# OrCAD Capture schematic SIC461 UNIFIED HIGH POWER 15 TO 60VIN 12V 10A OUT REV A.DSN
size B; title: SIC461 Demo High Power Unified Board 15 to 60Vin 12Vout 10A 300kHz; rev: A
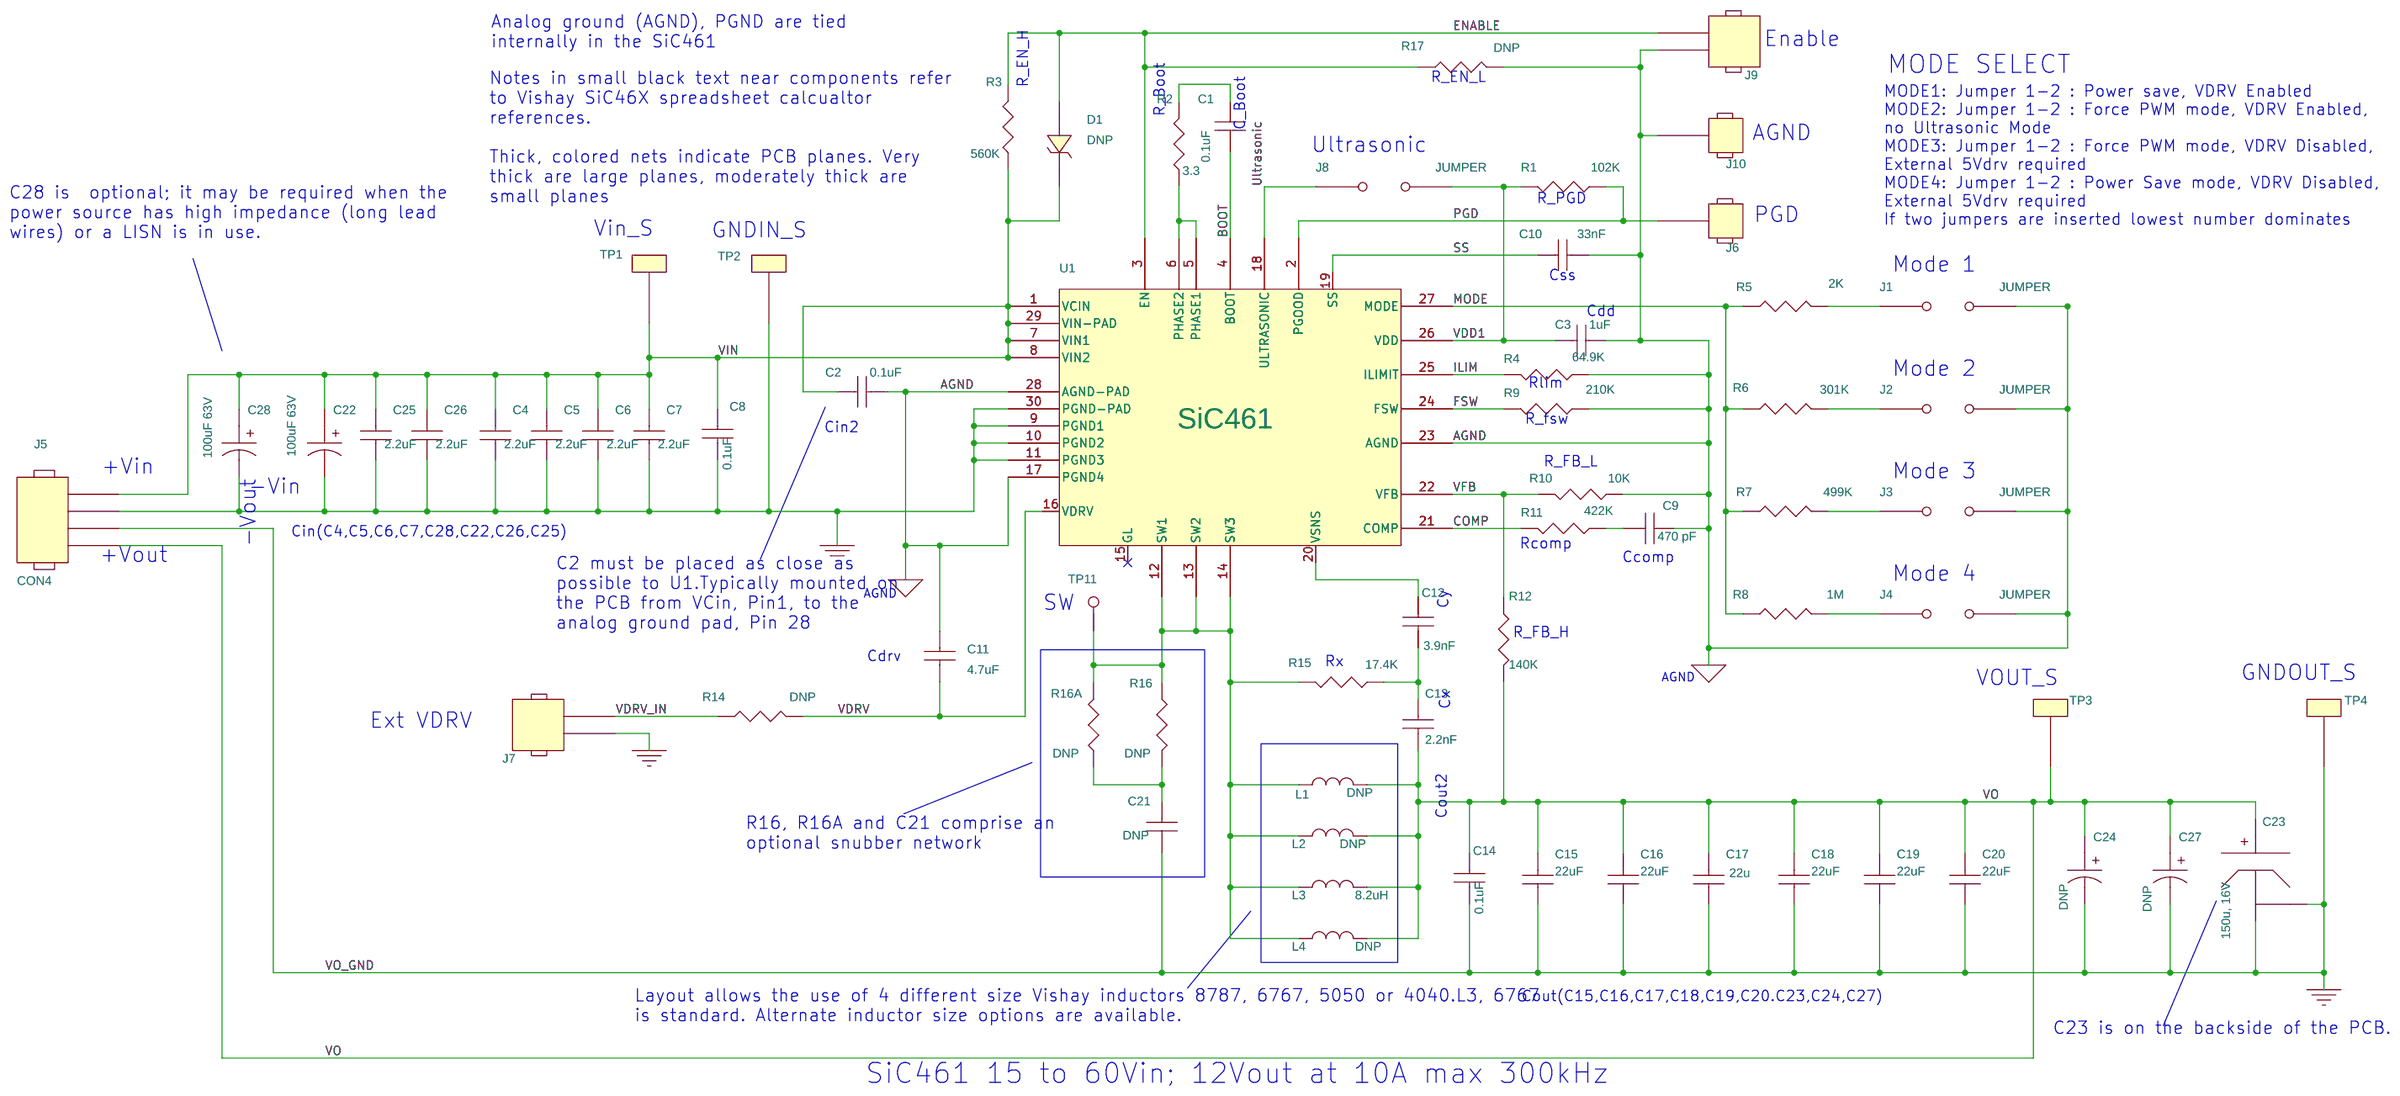
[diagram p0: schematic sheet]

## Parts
C1  0.1uF  [C0603]
C2  0.1uF  [C0603]
C3  1uF  [C0603]
C4  2.2uF  [C1210]
C5  2.2uF  [C1210]
C6  2.2uF  [C1210]
C7  2.2uF  [C1210]
C8  0.1uF  [C0603]
C9  470 pF  [C0603]
C10  33nF  [C0603]
C11  4.7uF  [C0603]
C12  3.9nF  [C0603]
C13  2.2nF  [C0805]
C14  0.1uF  [C0603]
C15  22uF  [C1206]
C16  22uF  [C1206]
C17  22u  [C1206]
C18  22uF  [C1206]
C19  22uF  [C1206]
C20  22uF  [C1206]
C21  DNP  [C0603]
C22  100uF 63V
C23  150u, 16V  [T_D27_7343]
C24  DNP
C25  2.2uF  [C1210]
C26  2.2uF  [C1210]
C27  DNP
C28  100uF 63V
D1  DNP
J1  JUMPER
J2  JUMPER
J3  JUMPER
J4  JUMPER
J5  CON4
J6  PGD  [5002]
J7  EN
J8  JUMPER
J9  EN
J10  GND  [5002]
L1  DNP  [IHLP-4040]
L2  DNP  [IHLP-5050]
L3  8.2uH  [IHLP-6767]
L4  DNP  [IHLP-5050]
R1  102K  [R0603]
R2  3.3  [R0603]
R3  560K  [R0603]
R4  64.9K  [R0603]
R5  2K  [R0603]
R6  301K  [R0603]
R7  499K  [R0603]
R8  1M  [R0603]
R9  210K  [R0603]
R10  10K  [R0603]
R11  422K  [R0603]
R12  140K  [R0603]
R14  DNP  [R0603]
R15  17.4K  [R0805]
R16  DNP  [R0603]
R16A  DNP  [R1210]
R17  DNP  [R0603]
TP1  test point  [5002]
TP2  test point  [5002]
TP3  test point  [5002]
TP4  test point  [5002]
TP11  5002  [PAD040_060_SQ]
U1  SiC461  [5mmx5mm]

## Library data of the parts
C1 C2 C8 C14 = CAP_NP: Ceramic Cap, 0.1uF,100volts, X7S, 10%, 0603; DIGI-KEY: 810-C1608X7S2A104K; Data sheet\: http://www.mouser.com/ds/2/400/lcc_commercial_general_en-837201.pdf; Description1: Ceramic Cap, 0.1uF,100volts, X7S, 10%, 0603; Description2: Ceramic Cap, 0.1uF,100volts, X7S, 10%, 0603; DigikeyMouser: 810-C1608X7S2A104K; Mfr: Murata Electronics; Mfr Part Number: C1608X7S2A104K080AB; PCB Footprint1: 0603; PCB Footprint2: 0603; Package: 0603; Package1: 0603; Package2: 0603; Tolerance: 10%
C3 = CAP_NP: Ceramic Cap, 1uF,50V, X7R,0603,10%; Comment: X7R; DIGI-KEY: 963-UMK107AB7105KA-T; Data sheet\: http://www.mouser.com/ds/2/396/mlcc11_hq_e-541564.pdf; Description1: Ceramic Cap, 1uF,50V, X7R,0603,10%; Description2: Ceramic Cap, 1uF,50V, X7R,0603,10%; DigikeyMouser: 963-UMK107AB7105KA-T; Manufacturer: Taiyo Yuden; Manufacturer Part: UMK107AB7105KA-T; Manufacturer Part1: UMK107AB7105KA-T; Manufacturer Part2: UMK107AB7105KA-T; Manufacturer1: Taiyo Yuden; Manufacturer2: Taiyo Yuden; Mfr: Taiyo Yuden; Mfr Part Number: UMK107AB7105KA-T; Package: 0603; Package1: 0603; Package2: 0603; Tolerance: 10%; Voltage: 50V
C4-C7 C25 C26 = CAP_NP: Ceramic Cap, 2.2uF,100volts, X7R, 10%, 1210; DIGI-KEY: 81-GRM32ER72A225KA5K; Data sheet\: http://www.mouser.com/ds/2/281/c02e-2905.pdf; Description1: Ceramic Cap, 2.2uF,100volts, X7R, 10%, 1210; Description2: Ceramic Cap, 2.2uF,100volts, X7R, 10%, 1210; DigikeyMouser: 81-GRM32ER72A225KA5K; Mfr: Murata Electronics; Mfr Part Number: GRM32ER72A225KA35K
C9 = CAP_NP: Ceramic Cap, 470 pF,50V,C0G,0603,5%; Comment: C0G; DIGI-KEY: 77-VJ0603A471JXAAC; Data sheet\: http://www.mouser.com/ds/2/427/vjcommercialseries-222796.pdf; Description1: Ceramic Cap, 1000pF,50V,C0G,0603,5%; Description2: Ceramic Cap, 1000pF,50V,C0G,0603,5%; DigikeyMouser: 77-VJ0603A471JXAAC; Manufacturer: Vishay; Manufacturer Part: VJ0603A471JXAAC; Manufacturer Part1: VJ0603A471JXAAC; Manufacturer Part2: VJ0603A471JXAAC; Manufacturer1: Vishay; Manufacturer2: Vishay; Mfr: Vishay; Mfr Part Number: VJ0603A471JXAAC; Package: 0603; Package1: 0603; Package2: 0603; Tolerance: 10%; Voltage: 50V
C10 = CAP_NP: Ceramic Cap, 0.033uF,50V,X7R,0603,10%; Comment: X7R; DIGI-KEY: 77-VJ0603Y333KXACBC; Data sheet\: http://www.mouser.com/ds/2/427/vjw1bcbascomseries-223529.pdf; Description1: Ceramic Cap, 0.033uF,50V,X7R,0603,10%; Description2: Ceramic Cap, 0.033uF,50V,X7R,0603,10%; DigikeyMouser: 77-VJ0603Y333KXACBC; Manufacturer: Vishay; Manufacturer Part: VJ0603Y333KXACW1BC; Manufacturer Part1: VJ0603Y333KXACW1BC; Manufacturer Part2: VJ0603Y333KXACW1BC; Manufacturer1: Vishay; Manufacturer2: Vishay; Mfr: Vishay / Vitramon; Mfr Part Number: VJ0603Y333KXACW1BC; Package: 0603; Package1: 0603; Package2: 0603; Tolerance: 10%; Voltage: 50V
C11 = CAP_NP: Ceramic Cap, 4.7uF,25V,X6S,10%,0603; Comment: X6S; DIGI-KEY: 81-GRM188C81E475KE1D; Data sheet\: http://www.mouser.com/ds/2/281/c02e-2905.pdf; Description1: Ceramic Cap, 4.7uF,25V,X6S,10%,0603; Description2: Ceramic Cap, 4.7uF,25V,X6S,10%,0603; DigikeyMouser: 81-GRM188C81E475KE1D; Mfr: Murata; Mfr Part Number: GRM188C81E475KE11D; Tolerance: 10%; Voltage: 25V
C12 = CAP_NP: Ceramic Cap, 3900pF,100V,X7R,0603, 5%; Comment: X7R; DIGI-KEY: 77-VJ0603Y392JXBCBC; Data sheet\: http://www.mouser.com/ds/2/427/vjw1bcbascomseries-223529.pdf; Description1: Ceramic Cap, 3900pF,100V,X7R,0603, 5%; Description2: Ceramic Cap, 3900pF,100V,X7R,0603, 5%; DigikeyMouser: 77-VJ0603Y392JXBCBC; Manufacturer: Vishay; Manufacturer Part: VJ0603Y392JXBCW1BC; Manufacturer Part1: VJ0603Y392JXBCW1BC; Manufacturer Part2: VJ0603Y392JXBCW1BC; Manufacturer1: Vishay; Manufacturer2: Vishay; Mfr: Vishay; Mfr Part Number: VJ0603Y392JXBCW1BC; Package: 0603; Package1: 0603; Package2: 0603; Tolerance: 5%; Voltage: 100V
C13 = CAP_NP: Ceramic Cap, 2200pF,100V,X7R,0805, 10%; Comment: X7R; DIGI-KEY: 77-VJ0805Y222KXBPBC; Data sheet\: http://www.mouser.com/ds/2/427/vjw1bcbascomseries-223529.pdf; Description1: Ceramic Cap, 2200pF,100V,X7R,0805, 10%; Description2: Ceramic Cap, 2200pF,100V,X7R,0805, 10%; DigikeyMouser: 77-VJ0805Y222KXBPBC; Manufacturer: Vishay; Manufacturer Part: VJ0805Y222KXBPW1BC; Manufacturer Part1: VJ0805Y222KXBPW1BC; Manufacturer Part2: VJ0805Y222KXBPW1BC; Manufacturer1: Vishay; Manufacturer2: Vishay; Mfr: Vishay / Vitramon; Mfr Part Number: VJ0805Y222KXBPW1BC; Package: 0805; Package1: 0805; Package2: 0805; Tolerance: 10%; Voltage: 100V
C15 C16 C18-C20 = CAP_NP: Ceramic Cap, 22uF,25volts,X7R,10%,1206; Comment: X7R; DIGI-KEY: 581-12061C225KAT2A; Data sheet\: http://www.mouser.com/ds/2/40/X7RDielectric-777024.pdf; Description1: Ceramic Cap, 22uF,25volts,X7R,10%,1206; Description2: Ceramic Cap, 22uF,25volts,X7R,10%,1206; DigikeyMouser: 581-12061C225KAT2A; Mfr: AVX Corporation; Mfr Part Number: 12061C225KAT2A; Tolerance: 10%; Voltage: 100V
C17 = CAP_NP: Ceramic Cap, 22uF,25volts,X7R,10%,1206; Comment: X7R; DIGI-KEY: 581-12061C225KAT2A; Data sheet\: http://www.mouser.com/ds/2/40/X7RDielectric-777024.pdf; Description1: Ceramic Cap, 22uF,25volts,X7R,10%,1206; Description2: Ceramic Cap, 22uF,25volts,X7R,10%,1206; DigikeyMouser: 581-12061C225KAT2A; Mfr: AVX Corporation; Mfr Part Number: 12061C225KAT2A; Tolerance: 10%; Value1: 22uF; Value2: 22uF; Voltage: 100V
C21 = CAP_NP: Comment: X7S; Data sheet\: http://www.digikey.com/product-detail/en/C1608X7S2A104K080AB/445-5201-2-ND/2116317; DigikeyMouser: 445-5201-2-ND; Mfr: TDK Corporation; Mfr Part Number: C1608X7S2A104K080AB; Package: 0603; Package1: 0603; Package2: 0603; Tolerance: 10%; Voltage: 100V
C22 C24 C27 C28 = CAP_POL: CAP, alum, 100uF, 63volt, 105C, 10x12, 4khr; DIGI-KEY: 594-2222-150-58101; Data sheet\: http://www.mouser.com/ds/2/427/150rmi-222630.pdf; DigikeyMouser: 594-2222-150-58101; Manufacturer: Vishay; Mfr: Vishay; Mfr Part Number: MAL215058101E3; Part Type: CAP POL; Rating: 63V; Tolerance: 20%
C23 = CAP,_TA-P,V,470u,_2V_0: Polymer SMD 16volts 150uF ESR 50mohm 7343; DIGI-KEY: 667-16TQC150MYF; Data sheet\: http://www.mouser.com/ds/2/315/AAA8000C54-931458.pdf; DigikeyMouser: 667-16TQC150MYF; Mfr: Panasonic; Mfr Part Number: 16TQC150MYF
D1 = DIODE_ZENER: DIGI-KEY: 78-BZX384C3V3-E3-08; Data sheet\: http://www.mouser.com/ds/2/427/bzx384-58924.pdf; DigikeyMouser: 78-BZX384C3V3-E3-08; Mfr: Vishay; Mfr Part Number: BZX384C3V3-E3-08
J1-J4 J8 = JUMPER: BREAKAWAY HDR VERT 2 pitch 100mils; DIGI-KEY: 538-22-28-4023; Data sheet\: http://www.mouser.com/ds/2/276/0022284023_PCB_HEADERS-228360.pdf; Description1: BREAKAWAY HDR VERT 2 pitch 100mils; Description2: BREAKAWAY HDR VERT 2pitch 100mils; DigikeyMouser: 538-22-28-4023; Manufacturer: Molex; Manufacturer Part: 22-28-4023; Manufacturer Part1: 22-28-4023; Manufacturer Part2: 22-28-4023; Manufacturer1: Molex; Manufacturer2: Molex; Mfr: Molex; Mfr Part Number: 22-28-4023
J5 = HEADER_4: TERMINAL BLOCK 3.81MM Horz 4POS; DIGI-KEY: 649-220327-D041B01LF; Data sheet\: http://www.mouser.com/ds/2/18/20020327-941783.pdf; Description1: T; DigikeyMouser: 649-220327-D041B01LF; Man: Amphenol Anytek; Mfr: Amphenol Anytek; Mfr Part Number: 20020327-D041B01LF; Rating: 10A
J6 J10 = HEADER_1: Circuit Board Hardware-PCB TEST POINT WHITE; Description1: Circuit Board Hardware-PCB TEST POINT WHITE; Description2: Circuit Board Hardware-PCB TEST POINT WHITE; Man1: Keystone Electronics; Man2: Keystone Electronics; Manufacturer: Keystone Electronics; Manufacturer1: Keystone Electronics; Manufacturer2: Keystone Electronics
J7 J9 = HEADER_2: BREAKAWAY HDR VERT 2 pitch 100mils; DIGI-KEY: 538-22-28-4023; Data sheet\: http://www.mouser.com/ds/2/276/0022284023_PCB_HEADERS-228360.pdf; Description1: BREAKAWAY HDR VERT 2 pitch 100mils; Description2: BREAKAWAY HDR VERT 2 pitch 100mils; DigikeyMouser: 538-22-28-4023; Manufacturer: Molex; Manufacturer Part: 22-28-4023; Manufacturer Part1: 22-28-4023; Manufacturer Part2: 22-28-4023; Manufacturer1: Molex; Manufacturer2: Molex; Mfr: Molex; Mfr Part Number: 22-28-4023
L1 = IND: INDUCTOR, 3.3uH,20%,14m DCR,18.6A Saturation; Current: 8A; Data sheet\: http://www.vishay.com/docs/34193/lp40dz01.pdf; Description1: INDUCTOR, 5.6uH,20%,19m DCR,16A Saturation; Description2: INDUCTOR, 10uH,20%,17.2m DCR,15.5A Saturation; DigikeyMouser: 541-1295-1-ND; Manufacturer: Vishay; Manufacturer Part: IHLP4040DZER3R3M11; Manufacturer Part1: IHLP4040DZER5R6M01; Manufacturer Part2: IHLP5050FDER100M01; Manufacturer1: Vishay; Manufacturer2: Vishay; Mfr: Vishay Dale; Mfr Part Number: IHLP4040DZER100M01; Package1: 4040; Package2: 5050; Value1: 5.6uH; Value2: 10uH
L2 = IND: INDUCTOR, 10uH,20%,4m DCR,28A Saturation; Current: 28A; DIGI-KEY: 70-IHLP8787MZER100M5A; Data sheet\: http://www.mouser.com/ds/2/427/ihlp8787mz5a-211370.pdf; Description1: INDUCTOR, 10uH,20%,4m DCR,28A Saturation; Description2: INDUCTOR, 10uH,20%,4m DCR,28A Saturation; DigikeyMouser: 70-IHLP8787MZER100M5A; Manufacturer: Vishay; Manufacturer Part: IHLP8787MZER100M5A; Manufacturer Part1: IHLP8787MZER100M5A; Manufacturer Part2: IHLP8787MZER100M5A; Manufacturer1: Vishay; Manufacturer2: Vishay; Mfr: Vishay Dale; Mfr Part Number: IHLP8787MZER100M5A; Package1: 8787; Package2: 8787; Value1: 10uH; Value2: 10uH
L3 = IND: INDUCTOR, 8.2uH,20%,8.1m DCR,18.0A Saturation; Current: 18A; DIGI-KEY: 70-IHLP6767GZER8R2M1; Data sheet\: http://www.mouser.com/ds/2/427/lp67gz11-270733.pdf; Description1: INDUCTOR, 8.2uH,20%,8.1m DCR,18.0A Saturation; Description2: INDUCTOR, 8.2uH,20%,8.1m DCR,18.0A Saturation; DigikeyMouser: 70-IHLP6767GZER8R2M1; Manufacturer: Vishay; Manufacturer Part: VJ0603Y122JXBCW1BC; Manufacturer Part1: VJ0603Y122JXBCW1BC; Manufacturer Part2: VJ0603Y122JXBCW1BC; Manufacturer1: Vishay; Manufacturer2: Vishay; Mfr: Vishay Dale; Mfr Part Number: IHLP6767GZER8R2M11; Package1: 6767; Package2: 8787; Value2: 10uH
L4 = IND: INDUCTOR, 3.3uH,20%,14m DCR,18.6A Saturation; Current: 8A; Data sheet\: http://www.vishay.com/docs/34193/lp40dz01.pdf; Description1: INDUCTOR, 5.6uH,20%,19m DCR,16A Saturation; Description2: INDUCTOR, 10uH,20%,17.2m DCR,15.5A Saturation; DigikeyMouser: 541-1295-1-ND; Manufacturer: Vishay; Manufacturer Part: IHLP4040DZER3R3M11; Manufacturer Part1: IHLP6767GZER150M5A; Manufacturer Part2: IHLP5050FDER100M01; Manufacturer1: Vishay; Manufacturer2: Vishay; Mfr: Vishay Dale; Mfr Part Number: IHLP4040DZER100M01; Package1: 4040; Package2: 5050; Value1: 5.6uH; Value2: 10uH
R1 = RESISTOR: SMD,102K,1%,0603; DIGI-KEY: 71-CRCW0603-102K-E3; Data sheet\: http://www.mouser.com/ds/2/427/dcrcwe3-109170.pdf; Description1: SMD,102K,1%,0603; Description2: SMD,102K,1%,0603; DigikeyMouser: 71-CRCW0603-102K-E3; Man: Vishay; Man Part Number: CRCW0603102KFKEA; Man Part Number1: CRCW0603102KFKEA; Man Part Number2: CRCW0603102KFKEA; Man1: Vishay; Man2: Vishay; Manufacturer: Vishay; Manufacturer Part: CRCW0603102KFKEA; Manufacturer Part1: CRCW0603102KFKEA; Manufacturer Part2: CRCW0603102KFKEA; Manufacturer1: Vishay; Manufacturer2: Vishay; Mfr: Vishay; Mfr Part Number: CRCW0603102KFKEA; PCB Footprint1: 0603; PCB Footprint2: 0603; Package: 0603; Package1: 0603; Package2: 0603
R2 = RESISTOR: SMD,3.3Ohm, 1% 0603; DIGI-KEY: 71-CRCW06033R30FKEA; Data sheet\: http://www.mouser.com/ds/2/427/dcrcwe3-109170.pdf; Description1: SMD,3.3Ohm, 1% 0603; Description2: SMD,3.3Ohm, 1% 0603; DigikeyMouser: 71-CRCW06033R30FKEA; Man: Vishay; Man Part Number: CRCW06033R30FKEA; Man Part Number1: CRCW06033R30FKEA; Man Part Number2: CRCW06033R30FKEA; Man1: Vishay; Man2: Vishay; Manufacturer: Vishay; Manufacturer Part: CRCW06030000ZSTA; Manufacturer Part1: CRCW06030000ZSTA; Manufacturer Part2: CRCW06030000ZSTA; Manufacturer1: Vishay; Manufacturer2: Vishay; Mfr: Vishay; Mfr Part Number: CRCW06033R30FKEA; PCB Footprint1: 0603; PCB Footprint2: 0603; Package: 0603; Package1: 0603; Package2: 0603
R3 = RESISTOR: SMD,560K,1%,0603; DIGI-KEY: 71-CRCW0603-560K-E3; Data sheet\: http://www.mouser.com/ds/2/427/dcrcwe3-109170.pdf; Description1: SMD,560K,1%,0603; Description2: SMD,560K,1%,0603; DigikeyMouser: 71-CRCW0603-560K-E3; Man: Vishay; Man Part Number: CRCW0603560KFKEA; Man Part Number1: CRCW0603560KFKEA; Man Part Number2: CRCW0603560KFKEA; Man1: Vishay; Man2: Vishay; Manufacturer: Vishay; Manufacturer Part: CRCW0603560KFKTA; Manufacturer Part1: CRCW0603560KFKTA; Manufacturer Part2: CRCW0603560KFKTA; Manufacturer1: Vishay; Manufacturer2: Vishay; Mfr: Vishay; Mfr Part Number: CRCW0603560KFKEA; PCB Footprint1: 0603; PCB Footprint2: 0603; Package: 0603; Package1: 0603; Package2: 0603
R4 = RESISTOR: SMD,64.9k,1%,0603; DIGI-KEY: 71-CRCW0603-64.9K; Data sheet\: http://www.digikey.com/product-detail/en/vishay-dale/CRCW04024K64FKED/541-4.64KLCT-ND/1183198; Description1: SMD,64.9K,1%,0603; Description2: SMD,64.9K,1%,0603; DigikeyMouser: 71-CRCW0603-64.9K; Manufacturer: Vishay; Manufacturer Part: CRCW060364K9FKTA; Manufacturer Part1: CRCW060364K9FKTA; Manufacturer Part2: CRCW060364K9FKTA; Manufacturer1: Vishay; Manufacturer2: Vishay; Mfr: Vishay Dale; Mfr Part Number: CRCW060364K9FKTA; Package: 0603; Package1: 0603; Package2: 0603; Tolerance: 1%
R5 = RESISTOR: SMD,2K,1%,0603; DIGI-KEY: 71-CRCW06032K00FKEB; Data sheet\: http://www.mouser.com/ds/2/427/dcrcwe3-109170.pdf; Description1: SMD,2K,1%,0603; Description2: SMD,2K,1%,0603; DigikeyMouser: 71-CRCW06032K00FKEB; Manufacturer: Vishay; Manufacturer Part: CRCW06032K00FKEB; Manufacturer Part1: CRCW06032K00FKEB; Manufacturer Part2: CRCW06032K00FKEB; Manufacturer1: Vishay; Manufacturer2: Vishay; Mfr: Vishay Dale; Mfr Part Number: CRCW06032K00FKEB; Package: 0603; Package1: 0603; Package2: 0603; Tolerance: 1%
R6 = RESISTOR: SMD,301K,1%,0603; DIGI-KEY: 71-CRCW0603-301K-E3; Data sheet\: http://www.mouser.com/ds/2/427/dcrcwe3-109170.pdf; Description1: SMD,301K,1%,0603; Description2: SMD,301K,1%,0603; DigikeyMouser: 71-CRCW0603-301K-E3; Manufacturer: Vishay; Manufacturer Part: CRCW0603301KFKEA; Manufacturer Part1: CRCW0603301KFKEA; Manufacturer Part2: CRCW0603301KFKEA; Manufacturer1: Vishay; Manufacturer2: Vishay; Mfr: Vishay Dale; Mfr Part Number: CRCW0603301KFKEA; Package: 0603; Package1: 0603; Package2: 0603; Tolerance: 1%
R7 = RESISTOR: SMD,499K,1%,0603; DIGI-KEY: 71-CRCW0603-499K-E3; Data sheet\: http://www.mouser.com/ds/2/427/dcrcwe3-109170.pdf; Description1: SMD,499K,1%,0603; Description2: SMD,499K,1%,0603; DigikeyMouser: 71-CRCW0603-499K-E3; Manufacturer: Vishay; Manufacturer Part: CRCW0603499KFKEA; Manufacturer Part1: CRCW0603499KFKEA; Manufacturer Part2: CRCW0603499KFKEA; Manufacturer1: Vishay; Manufacturer2: Vishay; Mfr: Vishay Dale; Mfr Part Number: CRCW0603499KFKEA; Package: 0603; Package1: 0603; Package2: 0603; Tolerance: 1%
R8 = RESISTOR: SMD,1000K,1%,0603; DIGI-KEY: 71-RCG06031M00FKEA; Data sheet\: http://www.mouser.com/ds/2/427/rcge3-254226.pdf; Description1: SMD,1000K,1%,0603; Description2: SMD,1000K,1%,0603; DigikeyMouser: 71-RCG06031M00FKEA; Manufacturer: Vishay; Manufacturer Part: RCG06031M00FKEA; Manufacturer Part1: RCG06031M00FKEA; Manufacturer Part2: RCG06031M00FKEA; Manufacturer1: Vishay; Manufacturer2: Vishay; Mfr: Vishay Dale; Mfr Part Number: RCG06031M00FKEA; Package: 0603; Package1: 0603; Package2: 0603; Tolerance: 1%
R9 = RESISTOR: SMD,210K,1%,0603 100PPM; DIGI-KEY: 71-CRCW0603-210K-E3; Data sheet\: http://www.mouser.com/ds/2/427/dcrcwe3-109170.pdf; Description1: SMD,210K,1%,0603 100PPM; Description2: SMD,210K,1%,0603 100PPM; DigikeyMouser: 71-CRCW0603-210K-E3; Manufacturer: Vishay; Manufacturer Part: CRCW0603210KFKEA; Manufacturer Part1: CRCW0603210KFKEA; Manufacturer Part2: CRCW0603210KFKEA; Manufacturer1: Vishay; Manufacturer2: Vishay; Mfr: Vishay Dale; Mfr Part Number: CRCW0603210KFKEA; Package: 0603; Package1: 0603; Package2: 0603; Tolerance: 1%
R10 = RESISTOR: SMD,10K,1%,0603; DIGI-KEY: 71-CRCW0603-10K; Data sheet\: http://www.mouser.com/ds/2/427/dcrcwe3-109170.pdf; Description1: SMD,10K,1%,0603; Description2: SMD,10K,1%,0603; DigikeyMouser: 71-CRCW0603-10K; Manufacturer: Vishay; Manufacturer Part: CRCW060310K0FKTA; Manufacturer Part1: CRCW060310K0FKTA; Manufacturer Part2: CRCW060310K0FKTA; Manufacturer1: Vishay; Manufacturer2: Vishay; Mfr: Vishay Dale; Mfr Part Number: CRCW060310K0FKTA; Package: 0603; Package1: 0603; Package2: 0603; Tolerance: 1%
R11 = RESISTOR: SMD 1/10watt 422Kohms 1%,0603; DIGI-KEY: 71-CRCW0603-422K-E3; Data sheet\: http://www.mouser.com/ds/2/427/dcrcwe3-109170.pdf; Description1: SMD 1/10watt 422Kohms 1%,0603; Description2: SMD 1/10watt 422Kohms 1%,0603; DigikeyMouser: 71-CRCW0603-422K-E3; Manufacturer: Vishay; Manufacturer Part: CRCW0603422KFKEA; Manufacturer Part1: CRCW0603422KFKEA; Manufacturer Part2: CRCW0603422KFKEA; Manufacturer1: Vishay; Manufacturer2: Vishay; Mfr: Vishay Dale; Mfr Part Number: CRCW0603422KFKEA; Package: 0603; Package1: 0603; Package2: 0603; Tolerance: 1%
R12 = RESISTOR: SMD 1,10W 140K Ohms 1% 0603; DIGI-KEY: 71-CRCW0603-140K-E3; Data sheet\: http://www.mouser.com/ds/2/427/dcrcwe3-109170.pdf; Description1: SMD 1,10W 140K Ohms 1% 0603; Description2: SMD 1,10W 140K Ohms 1% 0603; DigikeyMouser: 71-CRCW0603-140K-E3; Manufacturer: Vishay; Manufacturer Part: CRCW0603140KFKEA; Manufacturer Part1: CRCW0603140KFKEA; Manufacturer Part2: CRCW0603140KFKEA; Manufacturer1: Vishay; Manufacturer2: Vishay; Mfr: Vishay Dale; Mfr Part Number: CRCW0603140KFKEA; Package: 0603; Package1: 0603; Package2: 0603; Tolerance: 1%
R14 R16 = RESISTOR: Data sheet\: http://www.mouser.com/ds/2/427/dcrcwe3-109170.pdf; DigikeyMouser: 541-4.64KLCT-ND; Mfr: Vishay Dale; Mfr Part Number: CRCW04024K64FKED; Package: 0603; Package1: 0603; Package2: 0603; Tolerance: 1%
R15 = RESISTOR: Resistors - SMD 1/8watt 17.4Kohms 1% 0805; DIGI-KEY: 71-CRCW080517K4FKEA; Data sheet\: http://www.mouser.com/ds/2/427/dcrcwe3-109170.pdf; Description1: Resistors - SMD 1/8watt 17.4Kohms 1% 0805; Description2: Resistors - SMD 1/8watt 17.4Kohms 1% 0805; DigikeyMouser: 71-CRCW080517K4FKEA; Mfr: Vishay Dale; Mfr Part Number: CRCW080517K4FKEA; Tolerance: 1%
R16A = RESISTOR: SMD,1.0K,1%,1210; DIGI-KEY: 71-CRCW12101K00FKEAH; Data sheet\: http://www.mouser.com/ds/2/427/crcwhpe3-46056.pdf; DigikeyMouser: 71-CRCW12101K00FKEAH; Manufacturer: Vishay; Manufacturer Part: CRCW12101K00FKEAHP; Mfr: Vishay Dale; Mfr Part Number: CRCW12101K00FKEAHP; Package: 1210; Tolerance: 1%
R17 = RESISTOR: Data sheet\: http://www.mouser.com/ds/2/427/dcrcwe3-109170.pdf; Package: 0603; Package1: 0603; Package2: 0603
TP1-TP4 = TEST_POINT: Circuit Board Hardware-PCB TEST POINT WHITE; Description1: Circuit Board Hardware-PCB TEST POINT WHITE; Description2: Circuit Board Hardware-PCB TEST POINT WHITE; Man: Keystone Electronics; Man Part Number1: Keystone Electronics 5002; Man Part Number2: Keystone Electronics 5002; Man1: Keystone Electronics; Man2: Keystone Electronics; Manufacturer: Keystone Electronics; Manufacturer1: Keystone Electronics; Manufacturer2: Keystone Electronics
TP11 = TP_0: TST PNT,WHT INSL,0.050"ID; DIGI-KEY: 5002K-ND; Mfr: KEYSTONE ELECTRONICS CORP.; Part Type: TP
U1 = SiC462CD-T1-GE3_27: 4.5~60V,10A, High Voltage microBuck; DIGI-KEY: 78-SIC462ED-T1-GE3; Data sheet\: http://www.mouser.com/ds/2/427/sic462-1061838.pdf; Description1: 4.5~60V,10A, High Voltage microBuck; Description2: 4.5~60V,10A, High Voltage microBuck; DigikeyMouser: 78-SIC462ED-T1-GE3; Man: Vishay; Man Part Number: SiC461ED-T1-GE3; Man Part Number1: SiC461ED-T1-GE3; Man Part Number2: SiC461ED-T1-GE3; Man1: Vishay; Man2: Vishay; Mfr: Vishay; Mfr Part Number: SiC461ED-T1-GE3

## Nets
GND: C4.1 C5.1 C6.1 C7.1 C8.2 C14.2 C15.1 C16.1 C17.1 C18.1 C19.1 C20.1 C21.2 C22.2 C23.2 C23.3 C24.2 C25.1 C26.1 C27.2 C28.2 J5.2 J5.3 J7.2 TP2.1 TP4.1 U1.9(PGND1) U1.10(PGND2) U1.11(PGND3) U1.30(PGND-PAD)
GND_SIGNAL: C2.2 C3.1 C9.1 C10.2 C11.1 J1.1 J2.1 J3.1 J4.1 J9.2 J10.1 R4.1 R9.1 R10.1 R17.1 U1.17(PGND4) U1.23(AGND) U1.28(AGND-PAD)
VDD1: C3.2 J8.1 R1.2 U1.26(VDD)
VIN: C2.1 C4.2 C5.2 C6.2 C7.2 C8.1 C22.1 C25.2 C26.2 C28.1 D1.1(CATHODE) J5.1 R3.1 TP1.1 U1.1(VCIN) U1.7(VIN1) U1.8(VIN2) U1.29(VIN-PAD)
BOOT: C1.2 U1.4(BOOT)
COMP: R11.2 U1.21(COMP)
ENABLE: D1.2(ANODE) J9.1 R3.2 R17.2 U1.3(EN)
FSW: R9.2 U1.24(FSW)
ILIM: R4.2 U1.25(ILIMIT)
MODE: R5.1 R6.1 R7.1 R8.1 U1.27(MODE)
PGD: J6.1 R1.1 U1.2(PGOOD)
SS: C10.1 U1.19(SS)
Ultrasonic: J8.2 U1.18(ULTRASONIC)
VDRV: C11.2 R14.2 U1.16(VDRV)
VDRV_IN: J7.1 R14.1
VFB: R10.2 R12.1 U1.22(VFB)
VO: C13.2 C14.1 C15.2 C16.2 C17.2 C18.2 C19.2 C20.2 C23.1 C24.1 C27.1 J5.4 L1.1(A) L2.1(A) L3.1(A) L4.1(A) R12.2 TP3.1
N16770186: R2.1 U1.5(PHASE1) U1.6(PHASE2)
N16770229: C1.1 R2.2
N16771868: C9.2 R11.1
N16772198: J1.2 R5.2
N16772202: J2.2 R6.2
N16772206: J3.2 R7.2
N16773012: C12.2 C13.1 R15.1
N16775181: L1.2(B) L2.2(B) L3.2(B) L4.2(B) R15.2 R16.1 R16A.1 TP11.1 U1.12(SW1) U1.13(SW2) U1.14(SW3)
N16812890: C21.1 R16.2 R16A.2
N16829136: J4.2 R8.2
N16842327: C12.1 U1.20(VSNS)

Not connected (* = marked no-connect by the designer): U1 15(GL)*

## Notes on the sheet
- Analog ground (AGND), PGND are tied
  internally in the SiC461
- Enable
- MODE SELECT
- Notes in small black text near components refer
  to Vishay SiC46X spreadsheet calcualtor
  references.
- R_EN_L
- R_EN_H
- MODE1: Jumper 1-2 : Power save, VDRV Enabled
  MODE2: Jumper 1-2 : Force PWM mode, VDRV Enabled,
  no Ultrasonic Mode
  MODE3: Jumper 1-2 : Force PWM mode, VDRV Disabled,
  External 5Vdrv required
  MODE4: Jumper 1-2 : Power Save mode, VDRV Disabled,
  External 5Vdrv required
  If two jumpers are inserted lowest number dominates
- R_Boot
- C_Boot
- AGND
- Thick, colored nets indicate PCB planes. Very
  thick are large planes, moderately thick are
  small planes
- Ultrasonic
- C28 is  optional; it may be required when the
  power source has high impedance (long lead
  wires) or a LISN is in use.
- R_PGD
- PGD
- Vin_S
- GNDIN_S
- Mode 1
- Css
- Cdd
- Rlim
- Mode 2
- R_fsw
- +Vin
- Cin2
- R_FB_L
- -Vin
- Mode 3
- Cin(C4,C5,C6,C7,C28,C22,C26,C25)
- Rcomp
- +Vout
- -Vout
- C2 must be placed as close as
  possible to U1.Typically mounted on
  the PCB from VCin, Pin1, to the
  analog ground pad, Pin 28
- Ccomp
- Mode 4
- AGND
- SW
- Cy
- R_FB_H
- Cdrv
- Rx
- AGND
- VOUT_S
- GNDOUT_S
- Ext VDRV
- Cx
- R16, R16A and C21 comprise an
  optional snubber network
- Cout2
- Layout allows the use of 4 different size Vishay inductors 8787, 6767, 5050 or 4040.L3, 6767
  is standard. Alternate inductor size options are available.
- Cout(C15,C16,C17,C18,C19,C20.C23,C24,C27)
- C23 is on the backside of the PCB.
- SiC461 15 to 60Vin; 12Vout at 10A max 300kHz
